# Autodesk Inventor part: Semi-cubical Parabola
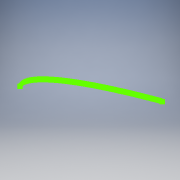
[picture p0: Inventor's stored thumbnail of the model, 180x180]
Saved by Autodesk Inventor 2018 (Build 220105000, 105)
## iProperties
Created: 2008-02
Part Number: Semi-cubical Parabola
Document SubType Name: Modeling
Designer: Autodesk, Inc.
Density: 1 g/cm^3
Material: Generic
Appearance: Default
Author: Autodesk, Inc.
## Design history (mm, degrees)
sketch "Sketch1"
  geometry: 301 further points
  constraints: 301 other
